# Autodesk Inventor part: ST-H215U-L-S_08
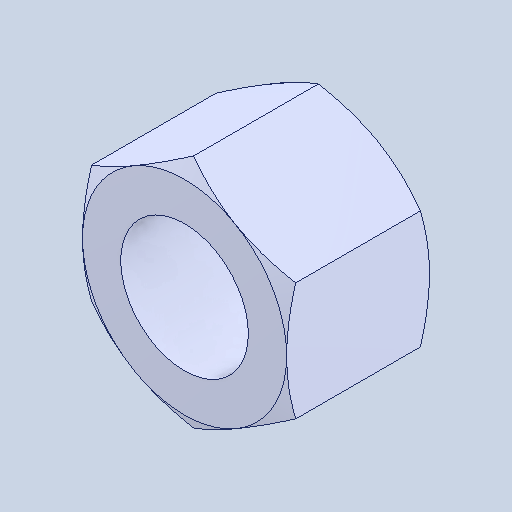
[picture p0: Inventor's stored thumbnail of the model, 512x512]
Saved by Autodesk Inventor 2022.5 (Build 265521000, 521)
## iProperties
Created: 2024-07
Part Number: ST-H215U-L-S_08
Material: 一般
Document SubType Name: Modeling
Designer: ImaoCorp
Density: 1 g/cm^3
Appearance: 既定
Author: ImaoCorp
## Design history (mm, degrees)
feature "ST-H215U-L-S_08"
node "ソリッド1"
